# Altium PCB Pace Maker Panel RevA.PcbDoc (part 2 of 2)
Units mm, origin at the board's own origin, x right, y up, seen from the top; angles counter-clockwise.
Board outline 150.47 x 78.27 mm, 2 copper layers (Top Copper, Bottom Copper), stack 1.57 mm thick; 193 components, 124 nets, 564 pads, 154 vias.
Unrouted connection lines stored in the file: 2.
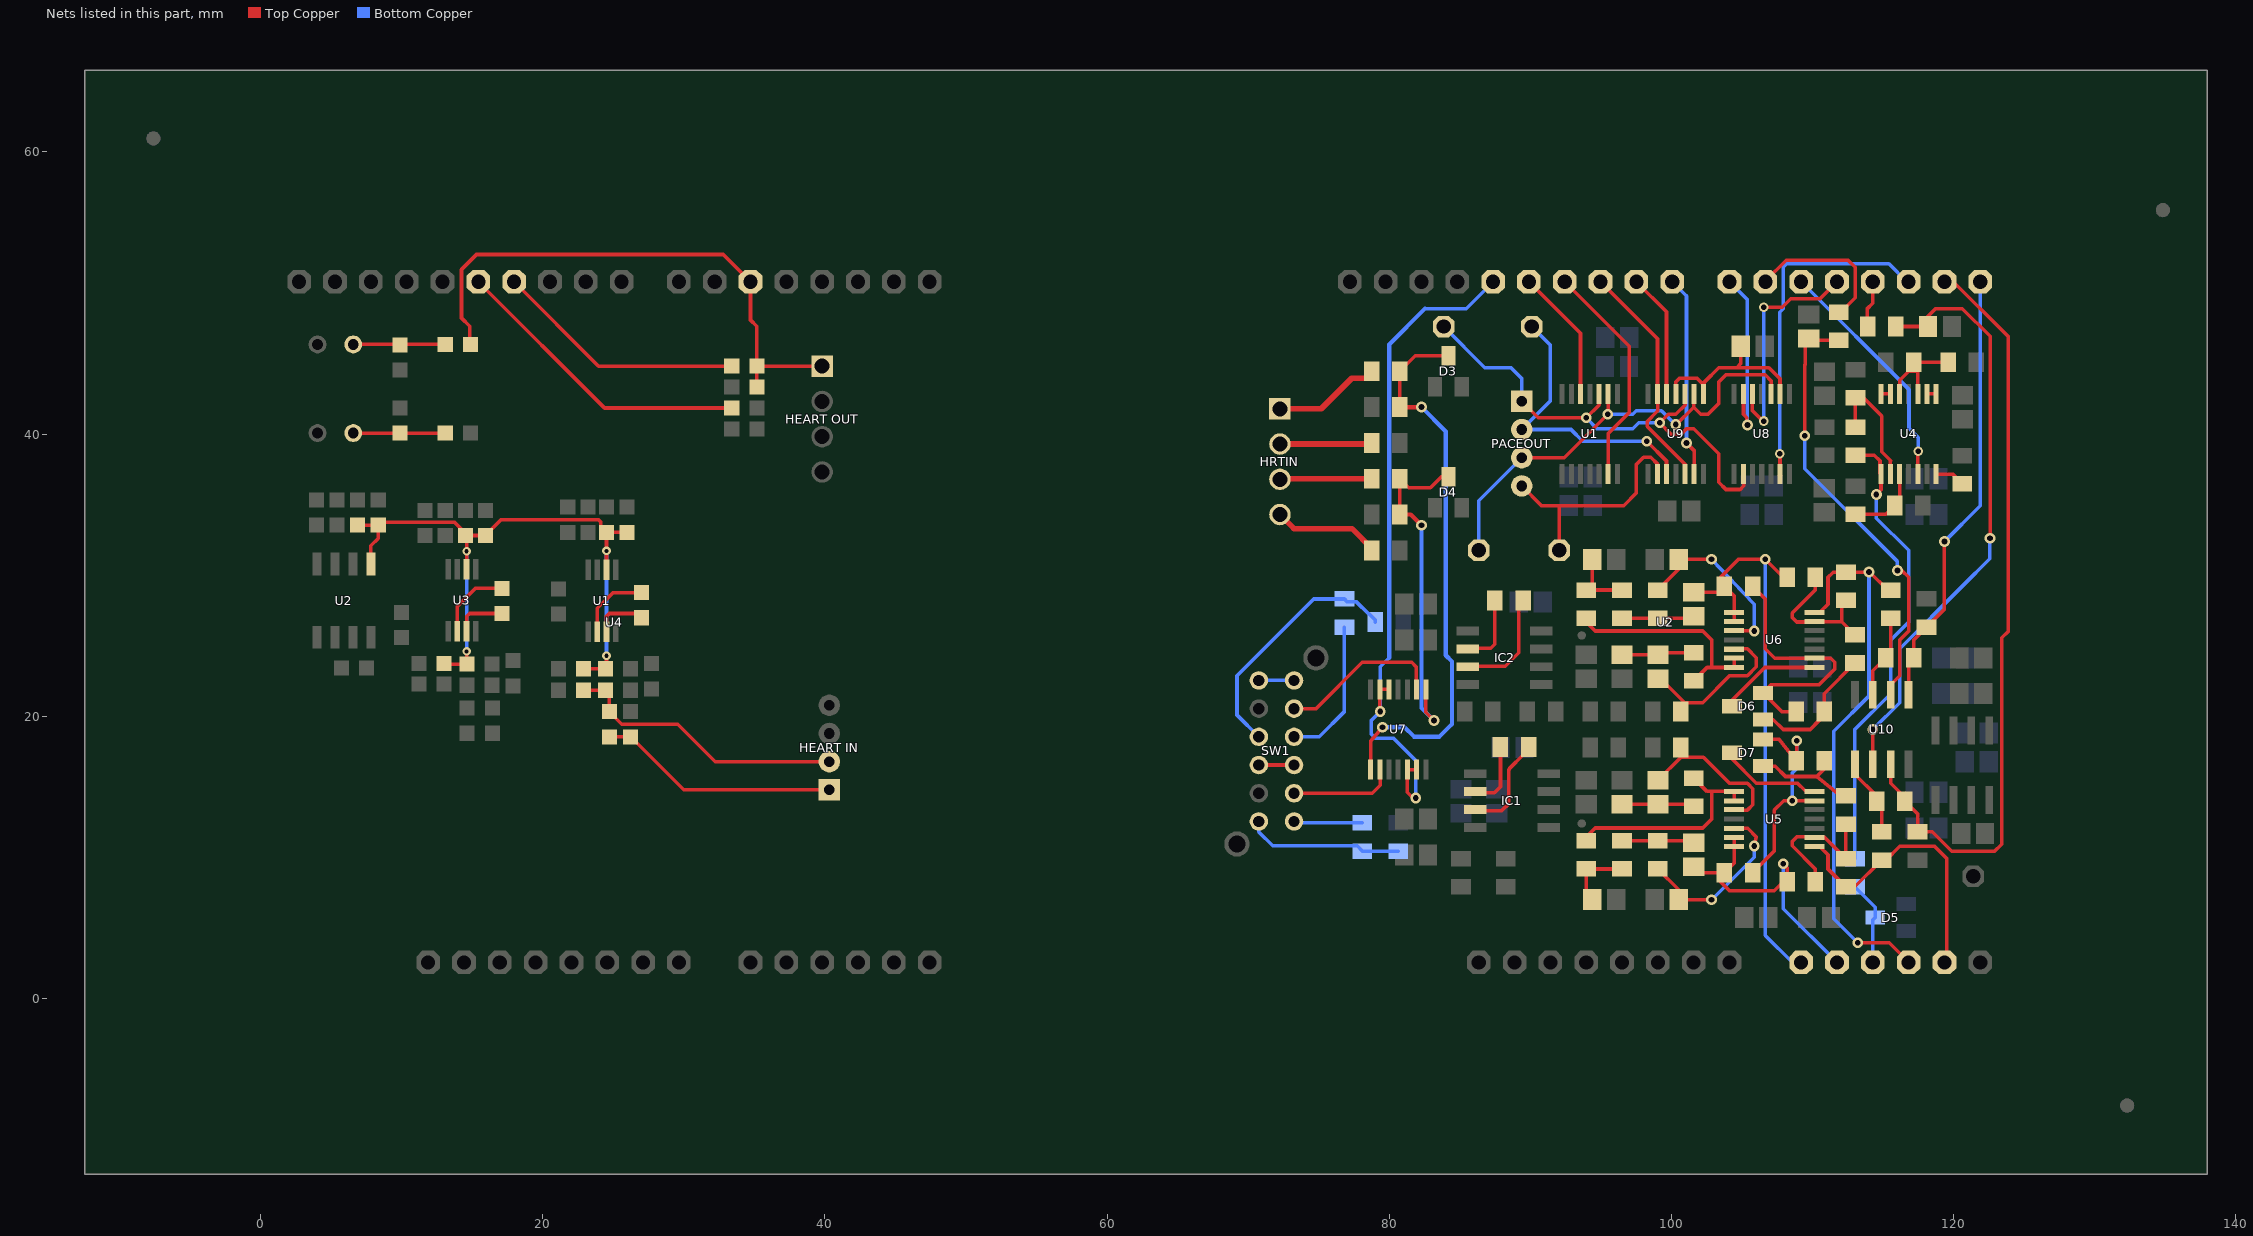
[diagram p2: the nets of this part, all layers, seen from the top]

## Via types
v1: diameter 0.762/0.762 (per signal layer), hole 0.406, Top Copper to Bottom Copper, 126 vias
v2: diameter 0.61, hole 0.305, Top Copper to Bottom Copper, 10 vias
v3: diameter 0.635, hole 0.381, Top Copper to Bottom Copper, 9 vias
v4: diameter 0.686, hole 0.33, Top Copper to Bottom Copper, 5 vias
v5: diameter 0.686, hole 0.381, Top Copper to Bottom Copper, 4 vias

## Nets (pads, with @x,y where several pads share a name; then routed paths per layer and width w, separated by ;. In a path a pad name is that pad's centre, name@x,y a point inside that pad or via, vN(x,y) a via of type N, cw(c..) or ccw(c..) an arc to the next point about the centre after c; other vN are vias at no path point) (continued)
NetC22_1: C22.1 U8.2 U9.8 U9.11 | length 13.4
  Top Copper w0.254: U9.11@100.33,42.85 100.33,43.688 100.584,43.942 101.854,43.942 102.286,43.51 U9.8@102.286,42.85 102.362,42.926 102.362,43.688 103.378,44.704 104.648,44.704 ; C22.1@104.941,46.228 104.941,44.997 104.648,44.704 ; U8.2@107.721,42.85 107.721,43.917 106.934,44.704 104.648,44.704
NetC23_2: C23.2 C25.1 R27.1 | length 5.1
  Top Copper w0.254: C23.2@96.52,13.755 C25.1@99.06,13.755 101.45,13.755 R27.1@101.6,13.605
NetC24_2: C24.2 C26.1 R28.1 | length 5.1
  Top Copper w0.254: C24.2@96.52,24.345 C26.1@99.06,24.345 99.21,24.495 R28.1@101.6,24.495
NetC25_2: C25.2 R25.2 U5.3 | length 11.7
  Top Copper w0.254: C25.2@99.06,15.455 R25.2@100.695,17.09 ; R25.2@100.695,17.78 R25.2@100.695,17.09 ; U5.3@104.47,13.36 104.496,13.335 105.41,13.335 105.791,13.716 105.791,14.859 105.41,15.24 104.14,15.24 102.29,17.09 R25.2@100.695,17.09
NetC26_2: C26.2 R26.2 U6.12 | length 12
  Top Copper w0.254: C26.2@99.06,22.645 99.275,22.645 R26.2@100.965,20.955 ; R26.2@100.695,20.32 100.965,20.59 R26.2@100.965,20.955 ; U6.12@104.47,24.74 104.496,24.765 105.41,24.765 106.045,24.13 106.045,23.495 105.41,22.86 104.14,22.86 102.235,20.955 R26.2@100.965,20.955
NetC29_1: C29.1 R29.2 R31.1 | length 4.9
  Top Copper w0.254: C29.1@94.4,6.985 93.98,7.405 R29.2@93.98,9.16 R31.1@96.52,9.16
NetC30_1: C30.1 R30.2 R32.1 | length 4.9
  Top Copper w0.254: C30.1@94.4,31.115 94.4,29.36 R30.2@93.98,28.94 R32.1@96.52,28.94
NetC31_1: C31.1 R33.2 U5.5 | length 12.7
  Top Copper w0.254: R33.2@99.06,9.16 100.545,7.675 C31.1@100.545,6.985 v1(102.87,6.985) ; U5.5@104.47,12.04 105.435,12.04 106.045,11.43 v1(105.886,10.795)
  Bottom Copper w0.254: v1(102.87,6.985) 105.886,10.001 v1(105.886,10.795)
NetC32_1: C32.1 R34.2 U6.10 | length 13.1
  Top Copper w0.254: R34.2@99.06,28.94 100.545,30.425 C32.1@100.545,31.115 v1(102.87,31.115) ; U6.10@104.47,26.06 106.02,26.06 v1(105.886,26.035)
  Bottom Copper w0.254: v1(102.87,31.115) 105.886,27.94 v1(105.886,26.035)
NetC34_1: C34.1 R31.2 R33.1 | length 5.1
  Top Copper w0.254: R31.2@96.52,11.16 R33.1@99.06,11.16 101.45,11.16 C34.1@101.6,11.01
NetC34_2: C34.2 R36.1 R40.1 U2.A1 U5.6 U5.7 | length 21.5
  Top Copper w0.254: C34.2@101.6,9.31 102.02,8.89 R36.1@103.775,8.89 ; U5.6@104.47,11.405 U5.7@104.47,10.744 104.47,9.585 R36.1@103.775,8.89 ; v1(107.95,9.525) 108.22,9.255 R40.1@108.22,8.255 108.22,8.525 107.315,7.62 104.14,7.62 103.505,8.255 103.505,8.62 R36.1@103.775,8.89
  Bottom Copper w0.254: v1(107.95,9.525) 107.95,6.35 U2.A1@111.76,2.54
NetC35_1: C35.1 R32.2 R34.1 | length 5.1
  Top Copper w0.254: R32.2@96.52,26.94 R34.1@99.06,26.94 101.45,26.94 C35.1@101.6,27.09
NetC35_2: C35.2 R35.1 R39.1 U2.A0 U6.8 U6.9 | length 41.7
  Top Copper w0.254: C35.2@101.6,28.79 103.355,28.79 R35.1@103.775,29.21 ; U6.9@104.47,26.695 U6.8@104.47,27.356 104.47,28.515 R35.1@103.775,29.21 ; R39.1@108.22,29.845 107.95,29.845 v1(106.68,31.115) 104.775,31.115 103.505,29.845 103.505,29.48 R35.1@103.775,29.21
  Bottom Copper w0.254: v1(106.68,31.115) 106.68,4.445 108.585,2.54 U2.A0@109.22,2.54
NetC37_1: C37.1 R41.1 U10.6 | length 42.2
  Top Copper w0.254: U10.6@114.3,16.586 v1(114.3,19.05) ; R41.1@115.935,47.625 C37.1@118.213,47.625 118.213,48.363 118.745,48.895 120.65,48.895 122.618,46.926 122.618,32.619 v1(122.604,32.604)
  Bottom Copper w0.254: v1(114.3,19.05) 116.205,20.955 116.205,24.765 120.666,29.226 122.604,31.164 v1(122.604,32.604)
NetC38_1: C38.1 R42.1 U10.2 | length 31.3
  Top Copper w0.254: v1(109.474,39.878) 109.474,44.895 109.498,44.919 109.498,46.52 C38.1@109.753,46.775 109.891,46.638 R42.1@111.887,46.638 ; U10.2@115.57,21.514 115.57,22.225 116.205,22.86 116.205,25.4 116.84,26.035 116.84,29.845 116.364,30.321 v1(116.046,30.321)
  Bottom Copper w0.254: v1(109.474,39.878) 109.474,37.529 116.046,30.956 v1(116.046,30.321)
NetD3_3: D3.3 R1.2@80.756,44.45 R5.2@80.756,41.91 U7.8 | length 40.5
  Top Copper w0.254: U7.8@78.689,16.205 78.689,18.205 v1(79.534,19.209) ; R5.2@80.756,41.91 R1.2@80.756,44.45 81.856,45.55 D3.3@84.201,45.55 D3.3@84.371,45.72
  Top Copper w0.305: R5.2@80.756,41.91 v1(82.296,41.91)
  Bottom Copper w0.305: v1(79.534,19.209) 81.097,19.209 81.764,18.542 83.566,18.542 84.455,19.431 84.455,23.876 84.023,24.308 84.023,40.183 v1(82.296,41.91)
NetD4_3: D4.3 R3.2@80.756,36.83 R6.2@80.756,34.29 U7.1 | length 25.1
  Top Copper w0.254: R6.2@80.756,34.29 R3.2@80.756,36.83 81.391,36.195 82.931,36.195 83.714,36.978 D4.3@84.201,36.978 ; U7.1@82.601,21.895 82.601,20.269 v1(83.185,19.685)
  Top Copper w0.305: R6.2@80.756,34.29 81.534,34.29 v1(82.296,33.528)
  Bottom Copper w0.305: v1(82.296,33.528) 82.296,20.574 v1(83.185,19.685)
NetD5_3: D5.3 R55.1 U2.A2 | length 6
  Bottom Copper w0.254: R55.1@113.03,7.89 114.47,6.45 D5.3@114.47,5.715 114.3,5.545 U2.A2@114.3,2.54
NetD6_1: D6.1 R37.2 R43.1 | length 9.7
  Top Copper w0.254: D6.1@106.51,19.751 107.249,19.751 107.95,19.05 109.855,19.05 110.49,19.685 110.49,19.955 R37.2@110.855,20.32 110.855,21.59 R43.1@113.03,23.765
NetD6_2: D6.2 R35.2 R37.1 U6.2 | length 19.3
  Top Copper w0.254: R35.2@105.775,29.21 106.68,28.305 106.68,24.765 107.34,24.105 U6.2@110.16,24.105 111.309,24.105 111.601,23.812 111.601,23.336 110.49,22.225 107.084,22.225 D6.2@106.51,21.651 107.841,20.32 R37.1@108.855,20.32
NetD6_3: D6.3 U6.1 | length 7.4
  Top Copper w0.254: D6.3@104.31,20.701 104.14,20.871 104.14,20.955 106.629,23.444 U6.1@110.16,23.444
NetD7_1: D7.1 R38.2 R44.1 | length 8.4
  Top Copper w0.254: D7.1@106.51,16.449 107.376,16.449 108.109,15.716 110.331,15.716 ; R38.2@110.855,16.828 111.125,16.875 111.125,16.51 110.331,15.716 ; R44.1@112.395,14.335 112.03,14.335 110.331,15.716
NetD7_2: D7.2 R36.2 R38.1 U5.13 | length 17.1
  Top Copper w0.254: R36.2@105.775,8.89 107.315,10.43 107.315,13.335 107.975,13.995 v1(108.585,13.995) U5.13@110.16,13.995 ; D7.2@106.51,18.349 107.651,18.349 R38.1@108.855,16.828 108.902,17.192 v1(108.902,18.256)
  Bottom Copper w0.254: v1(108.585,13.995) 108.585,15.967 108.902,16.285 v1(108.902,18.256)
NetD7_3: D7.3 U5.14 | length 7.2
  Top Copper w0.254: D7.3@104.31,17.399 104.31,16.975 106.045,15.24 108.966,15.24 109.499,14.707 110.109,14.707 U5.14@110.16,14.656
NetHRTIN_1: HRTIN.1 R1.1@78.756,44.45 | length 7.7
  Top Copper w0.406: HRTIN.1@72.263,41.79 75.191,41.79 77.354,43.953 78.409,43.953 78.756,44.3 R1.1@78.756,44.45
NetHRTIN_2: HRTIN.2 R2.1@78.756,39.37 | length 6.5
  Top Copper w0.406: HRTIN.2@72.263,39.29 78.676,39.29 R2.1@78.756,39.37
NetHRTIN_3: HRTIN.3 R3.1@78.756,36.83 | length 6.5
  Top Copper w0.406: HRTIN.3@72.263,36.79 72.303,36.83 R3.1@78.756,36.83
NetHRTIN_4: HRTIN.4 R4.1@78.756,31.75 | length 7.6
  Top Copper w0.406: HRTIN.4@72.263,34.29 73.26,33.293 77.362,33.293 78.756,31.9 R4.1@78.756,31.75
NetIC1_1: 
NetIC1_2: IC1.2 R19.1@87.9,17.8 | length 5
  Top Copper w0.254: IC1.2@85.9,14.57 87.47,14.57 87.9,15 R19.1@87.9,17.8
NetIC1_3: IC1.3 R19.2@89.9,17.8 | length 7.4
  Top Copper w0.254: IC1.3@85.9,13.3 88,13.3 88.5,13.8 88.5,16.145 cw(c88.754,16.145) 88.574,16.324 89.477,17.227 89.9,17.65 R19.2@89.9,17.8
NetIC1_8: 
NetIC2_1: 
NetIC2_2: IC2.2 R20.1@87.5,28.2 | length 4.9
  Top Copper w0.254: IC2.2@85.8,24.8 87.2,24.8 87.5,25.1 R20.1@87.5,28.2
NetIC2_3: IC2.3 R20.2@89.5,28.2 | length 7.4
  Top Copper w0.254: IC2.3@85.8,23.53 88.23,23.53 89.2,24.5 R20.2@89.2,28.1
NetIC2_8: 
NetJP2_1: JP2.1 PACEOUT.1 U1.3@94.894,42.85 U8.9 U9.10 | length 35
  Top Copper w0.254: PACEOUT.1@89.408,42.322 90.582,41.148 v1(93.98,41.148) 94.894,42.062 U1.3@94.894,42.85 ; U9.10@100.99,42.85 100.99,42.062 100.33,41.402 99.79,41.402 v1(99.187,40.799) 99.993,39.993 100.699,39.993 101.092,40.386 101.6,40.386 103.378,38.608 103.378,36.576 103.886,36.068 104.902,36.068 105.156,36.322 105.156,37.135 U8.9@105.131,37.16
  Bottom Copper w0.254: JP2.1@83.87,47.625 86.791,44.704 88.646,44.704 89.408,43.942 PACEOUT.1@89.408,42.322 ; v1(93.98,41.148) 94.742,40.386 97.282,40.386 97.695,40.799 v1(99.187,40.799)
NetJP3_1: JP3.1 PACEOUT.2 U9.3 | length 20.8
  Top Copper w0.254: v1(98.266,39.497) 99.67,38.094 U9.3@99.67,37.16
  Bottom Copper w0.254: JP3.1@90.12,47.625 91.44,46.305 91.44,42.354 PACEOUT.2@89.408,40.322 92.901,40.322 93.726,39.497 v1(98.266,39.497)
NetJP4_1: JP4.1 PACEOUT.3 U1.2@95.529,42.85 U8.3 U9.9 | length 33.6
  Top Copper w0.254: PACEOUT.3@89.408,38.322 92.424,38.322 v1(95.504,41.402) 95.529,41.427 U1.2@95.529,42.85 ; v1(100.33,40.679) 100.369,40.679 101.6,41.91 ; U9.9@101.625,42.85 101.6,42.824 101.6,41.91 ; U8.3@107.086,42.85 107.086,43.79 106.68,44.196 103.886,44.196 103.378,43.688 103.378,42.164 102.616,41.402 102.108,41.402 101.6,41.91
  Bottom Copper w0.254: JP4.1@86.36,31.75 86.36,35.274 PACEOUT.3@89.408,38.322 ; v1(95.504,41.402) 97.282,41.402 97.536,41.656 99.314,41.656 100.291,40.679 v1(100.33,40.679)
NetJP5_1: JP5.1 PACEOUT.4 U9.2 | length 16.9
  Top Copper w0.254: PACEOUT.4@89.408,36.322 90.805,34.925 92.075,34.925 ; JP5.1@92.075,31.75 92.075,34.925 ; U9.2@99.035,37.16 99.035,37.871 98.552,38.354 98.044,38.354 97.536,37.846 97.536,35.814 96.647,34.925 92.075,34.925
NetLED1_A: LED1.A LED3.A R13.2@13.074,46.355 | length 6.5
  Top Copper w0.254: LED3.A@6.553,46.355 10.211,46.355 R13.2@13.074,46.355
NetLED2_A: LED2.A LED4.A R14.2@13.074,40.068 | length 6.5
  Top Copper w0.254: LED4.A@6.553,40.068 LED2.A@9.855,40.068 R14.2@13.074,40.068
NetR4_1: R4.1@27,28.753 U1.2@23.861,25.99 | length 5.3
  Top Copper w0.254: U1.2@23.861,25.99 23.861,27.645 24.968,28.753 R4.1@27,28.753
NetR4_2: R4.2@27,26.975 U1.3@24.511,25.99 | length 3.9
  Top Copper w0.254: U1.3@24.511,25.99 24.511,27.071 24.717,27.277 26.547,27.277 26.594,27.229 26.695,27.229 R4.2@27.102,26.822
NetR7_1: R7.1@78.105,10.43 R8.2@80.645,10.43 SW1.1 | length 11.2
  Bottom Copper w0.254: SW1.1@70.765,12.53 70.765,11.785 71.755,10.795 77.74,10.795 R7.1@78.105,10.43 R8.2@80.645,10.43
NetR7_2: R7.2@78.105,12.43 SW1.7 | length 4.9
  Bottom Copper w0.254: SW1.7@73.265,12.53 73.365,12.43 R7.2@78.105,12.43
NetR9_1: R9.1@76.835,28.305 R10.2@79.01,26.67 SW1.4 | length 17.8
  Bottom Copper w0.254: SW1.4@70.765,18.53 69.215,20.08 69.215,22.86 74.66,28.305 R9.1@76.835,28.305 77.044,28.096 77.695,28.096 78.548,27.243 78.587,27.243 79.01,26.82 R10.2@79.01,26.67
NetR9_2: R9.2@76.835,26.305 SW1.10 | length 10.3
  Bottom Copper w0.254: SW1.10@73.265,18.53 75.045,18.53 76.835,20.32 R9.2@76.835,26.305
NetR10_1: R10.1@17.109,29.055 U3.2@13.934,26.006 | length 5.5
  Top Copper w0.254: U3.2@13.934,26.006 13.934,27.772 15.216,29.055 R10.1@17.109,29.055
NetR10_2: R10.2@17.109,27.277 U3.3@14.584,26.006 | length 3.7
  Top Copper w0.254: U3.3@14.584,26.006 14.605,26.027 14.605,27.071 14.811,27.277 R10.2@17.109,27.277
NetR12_2: R12.2@120.65,36.465 U4.7 | length 2.1
  Top Copper w0.254: U4.7@118.796,37.16 119.955,37.16 R12.2@120.65,36.465
NetR15_1: R15.1@33.39,44.813 U4.D11 | length 17.9
  Top Copper w0.254: U4.D11@17.958,50.8 23.945,44.813 R15.1@33.39,44.813
NetR16_1: R16.1@33.39,41.846 U4.D12 | length 21.7
  Top Copper w0.254: U4.D12@15.418,50.8 24.372,41.846 R16.1@33.39,41.846
NetR17_1: R17.1@113.081,34.306 R21.2 U4.3 | length 5.9
  Top Copper w0.254: R17.1@113.081,34.306 115.221,34.306 R21.2@115.84,34.925 ; R21.2@115.475,34.56 R21.2@115.84,34.925 ; U4.3@116.18,37.16 116.205,37.135 116.205,35.29 R21.2@115.84,34.925
NetR18_2: R18.2@113.068,42.561 R22.2 U4.2 | length 9
  Top Copper w0.254: R22.2@113.068,40.497 R18.2@113.068,42.561 113.395,42.815 114.935,41.275 114.935,38.735 115.57,38.1 115.545,38.075 U4.2@115.545,37.16
NetR22_1: R22.1 R55.2 U4.1 | length 32.8
  Top Copper w0.254: R22.1@113.068,38.497 114.411,38.497 114.808,38.1 114.808,37.236 U4.1@114.884,37.16 114.884,36.049 v1(114.554,35.719)
  Bottom Copper w0.254: R55.2@113.03,9.89 113.03,19.05 115.57,21.59 115.57,25.4 116.84,26.67 116.84,31.75 114.554,34.036 v1(114.554,35.719)
NetR27_2: R27.2 R29.1 U5.1 U5.2 | length 15.6
  Top Copper w0.254: R29.1@93.98,11.16 93.98,11.43 94.615,12.065 102.235,12.065 102.87,12.7 102.87,14.656 ; R27.2@101.6,15.605 102.549,14.656 102.87,14.656 ; U5.2@104.47,13.995 U5.1@104.47,14.656 102.87,14.656
NetR28_2: R28.2 R30.1 U6.13 U6.14 | length 15.6
  Top Copper w0.254: R30.1@93.98,26.94 93.98,26.67 94.615,26.035 102.235,26.035 102.87,25.4 102.87,23.444 ; R28.2@101.6,22.495 102.549,23.444 102.87,23.444 ; U6.13@104.47,24.105 U6.14@104.47,23.444 102.87,23.444
NetR39_2: R39.2 R43.2 R45.1 U6.6 | length 10.1
  Top Copper w0.254: R39.2@110.22,29.845 110.22,28.94 108.585,27.305 108.585,26.987 108.902,26.67 110.134,26.67 U6.6@110.16,26.695 112.1,26.695 ; R45.1@112.395,28.21 112.1,27.915 112.1,26.695 ; R43.2@113.03,25.765 112.1,26.695
NetR40_2: R40.2 R44.2 R46.1 U5.9 | length 10.6
  Top Copper w0.254: R40.2@110.22,8.255 110.22,9.16 108.585,10.795 108.585,11.112 108.902,11.43 110.134,11.43 U5.9@110.16,11.405 110.88,11.405 R46.1@112.395,9.89 R44.2@112.395,12.335
NetR41_2: R41.2 U2.D3 | length 3.9
  Top Copper w0.254: R41.2@113.935,47.625 113.894,47.666 113.894,48.87 114.3,49.276 U2.D3@114.3,50.8 U2.D3@113.935,50.435
NetR42_2: R42.2 U2.D6 | length 11
  Top Copper w0.254: U2.D6@106.68,50.8 106.68,50.851 108.153,52.324 112.547,52.324 113.055,51.816 113.055,49.656 112.46,49.061 R42.2@111.962,48.563
NetR45_2: R45.2 R48.2 U2.A3 U6.7 | length 40.5
  Top Copper w0.254: U6.7@110.16,27.356 110.541,27.356 111.125,27.94 111.125,29.845 111.49,30.21 R45.2@112.395,30.21 ; R45.2@112.442,30.162 R45.2@112.395,30.21 ; v1(113.23,3.92) 115.46,3.92 U2.A3@116.84,2.54 ; R48.2@115.57,28.94 115.364,28.94 114.094,30.21 v1(114.03,30.21) 113.53,30.21 R45.2@112.395,30.21
  Bottom Copper w0.254: v1(113.23,3.92) 111.53,5.62 111.53,18.92 114.03,21.42 v1(114.03,30.21)
NetR46_2: R46.2 R47.2 U2.A4 U5.8 | length 20.1
  Top Copper w0.254: U5.8@110.16,10.744 110.541,10.744 111.125,10.16 111.125,9.16 R46.2@112.395,7.89 113.03,7.89 R47.2@114.935,9.795 115.23,9.795 116.205,10.77 118.68,10.77 119.53,9.92 119.53,2.69 U2.A4@119.38,2.54
NetR47_1: R47.1 R49.2 U10.5 | length 5.6
  Top Copper w0.254: U10.5@113.03,16.586 113.03,15.875 114.57,14.335 R49.2@114.57,13.97 114.935,13.605 R47.1@114.935,11.795
NetR48_1: R48.1 R50.2 U10.3 | length 6.4
  Top Copper w0.254: U10.3@114.3,21.514 114.3,23.225 R50.2@115.205,24.13 ; R50.2@114.935,24.495 R50.2@115.205,24.13 ; R48.1@115.57,26.94 115.57,24.495 R50.2@115.205,24.13
NetR49_1: R49.1 R51.1 U2.D1 U10.7 | length 54.6
  Top Copper w0.254: U10.7@115.57,16.586 115.57,15.24 116.57,14.24 R49.1@116.57,13.97 117.475,13.065 R51.1@117.475,11.795 118.507,11.795 119.888,10.414 122.936,10.414 123.444,10.922 123.444,25.544 123.9,26 123.9,46.915 120.015,50.8 U2.D1@119.38,50.8
NetR50_1: R50.1 R52.1 U2.D0 U10.1 | length 31.4
  Top Copper w0.254: U10.1@116.84,21.514 116.84,23.86 R50.1@117.205,24.13 117.205,25.4 R52.1@118.11,26.305 119.38,27.575 v1(119.38,32.385)
  Bottom Copper w0.254: v1(119.38,32.385) 121.92,34.925 U2.D0@121.92,50.8
NetR53_1: R53.1 R54.2 U4.10 U4.12 | length 7.3
  Top Copper w0.254: U4.12@116.18,42.85 116.205,42.875 116.205,43.815 116.84,44.45 R54.2@117.5,44.45 ; U4.10@117.5,42.85 R54.2@117.5,44.45 ; R53.1@119.65,45.085 R54.2@117.205,45.085 117.5,44.79 R54.2@117.5,44.45
NetSW1_3: SW1.3 SW1.9 | length 2.5
  Top Copper w0.254: SW1.3@70.765,16.53 SW1.9@73.265,16.53
NetSW1_6: SW1.6 SW1.12 | length 2.5
  Bottom Copper w0.254: SW1.6@70.765,22.53 SW1.12@73.265,22.53
NetSW1_8: SW1.8 U7.9 | length 7.5
  Top Copper w0.254: SW1.8@73.265,14.53 78.815,14.53 79.375,15.09 79.375,15.575 U7.9@79.35,16.205
NetSW1_11: SW1.11 U7.2 | length 11.7
  Top Copper w0.254: SW1.11@73.265,20.53 74.823,20.53 78.105,23.812 81.597,23.812 81.915,23.495 81.915,22.525 U7.2@81.94,21.895
NetU1_5: U1.5@93.574,42.85 U2.D12 | length 9.5
  Top Copper w0.254: U2.D12@89.916,50.8 93.574,47.142 U1.5@93.574,42.85
NetU1_13: U1.13 U2.D11 | length 16.2
  Top Copper w0.254: U2.D11@92.456,50.8 97.028,46.228 97.028,41.528 95.529,40.029 U1.13@95.529,37.16
NetU2_D2: U2.D2 U8.13 | length 24.3
  Top Copper w0.254: v5(107.696,38.608) 107.721,38.583 U8.13@107.721,37.16
  Bottom Copper w0.254: v5(107.696,38.608) 107.696,48.641 107.95,48.895 107.95,51.816 108.204,52.07 115.443,52.07 116.713,50.8 U2.D2@116.84,50.8
NetU2_D4: U2.D4 U8.5 | length 16.3
  Top Copper w0.254: U8.5@105.766,42.85 105.766,41.656 106.502,40.919 v5(106.578,40.919) ; v5(106.578,48.997) 107.874,48.997 108.475,49.598 110.558,49.598 U2.D4@111.76,50.8
  Bottom Copper w0.254: v5(106.578,40.919) v5(106.578,48.997)
NetU2_D5: U2.D5 U4.5 | length 17.1
  Top Copper w0.254: U4.5@117.5,37.16 117.5,38.76 v5(117.526,38.786)
  Bottom Copper w0.254: U2.D5@109.22,50.8 116.865,43.155 116.865,40.411 117.526,39.751 v5(117.526,38.786)
NetU2_D7: U2.D7 U8.6 | length 13
  Top Copper w0.254: U8.6@105.131,42.85 105.131,41.4 105.365,41.165 105.365,40.685 v1(105.41,40.64)
  Bottom Copper w0.254: U2.D7@104.14,50.8 105.41,49.53 v1(105.41,40.64)
NetU2_D8: U2.D8 U9.6 | length 15.5
  Top Copper w0.254: v1(101.092,39.37) 101.625,38.837 U9.6@101.625,37.16
  Bottom Copper w0.254: v1(101.092,39.37) 101.092,49.784 100.965,49.911 ; 100.965,49.911 U2.D8@100.076,50.8 100.965,49.911
NetU2_D9: U2.D9 U9.12 | length 8.8
  Top Copper w0.254: U2.D9@97.536,50.8 99.67,48.666 U9.12@99.67,42.85
NetU2_D10: U2.D10 U9.5 U9.13 | length 16.8
  Top Copper w0.254: U2.D10@94.996,50.8 99.035,46.761 U9.13@99.035,42.85 99.06,42.824 99.06,41.656 98.298,40.894 98.298,40.538 100.99,37.846 U9.5@100.99,37.16
NetU2_D13: U2.D13 U7.5 U7.6 U7.12 U7.13 | length 49.2
  Top Copper w0.254: v1(79.375,20.32) 79.35,20.345 U7.6@79.35,21.895 U7.5@79.985,21.895 ; v1(81.9,14.2) 81.685,14.2 81.28,14.605 81.28,15.575 U7.12@81.305,16.205 U7.13@81.94,16.205
  Bottom Copper w0.254: 80.01,24.13 79.375,23.495 v1(79.375,20.32) 78.74,19.685 78.74,18.732 79.057,18.415 80.328,18.415 81.915,16.828 81.9,16.812 v1(81.9,14.2) ; 82.55,48.895 85.471,48.895 U2.D13@87.376,50.8
  Bottom Copper w0.305: 80.01,24.13 80.01,46.355 82.55,48.895
NetU4_8: U4.8 U4.9 | length 0.7
  Top Copper w0.254: U4.9@118.135,42.85 U4.8@118.796,42.85
NetU4_13: U4.13 U4.14 | length 0.7
  Top Copper w0.254: U4.14@114.884,42.85 U4.13@115.545,42.85
VENT+: "HEART IN.1" R1.2@26.226,18.532 R3.2@24.717,18.532 | length 17.2
  Top Copper w0.254: R3.2@24.717,18.532 R1.2@26.226,18.532 29.988,14.769 40.31,14.769
VENT-: "HEART IN.2" C4.1@22.891,21.834 R3.1@24.717,20.31 R5.1@24.447,21.834 | length 20.3
  Top Copper w0.254: C4.1@22.891,21.834 R5.1@24.447,21.834 24.717,21.565 R3.1@24.717,20.31 25.596,19.431 29.566,19.431 32.228,16.769 40.31,16.769
VENT_NAT: "HEART OUT.1" R13.1@14.852,46.355 R15.2@35.168,44.813 R17.2@35.168,43.329 U4.D5 | length 39.6
  Top Copper w0.254: R13.1@14.852,46.355 14.811,46.396 14.811,47.636 14.224,48.223 14.224,51.664 15.291,52.73 32.791,52.73 U4.D5@34.722,50.8 34.722,48.082 35.168,47.636 R15.2@35.168,44.813 ; R17.2@35.168,43.329 R15.2@35.168,44.813 ; 39.807,44.813 36.195,44.813 R15.2@35.168,44.813
VREF: C5.2@24.511,33.034 C6.2@25.961,33.034 C10.2@8.324,33.542 C11.2@6.862,33.542 C15.2@15.919,32.806 C16.2@14.496,32.806 R2.1@24.447,23.358 R6.2@22.891,23.358 R8.1@14.623,23.678 R12.2@12.979,23.714 U1.6@24.511,30.39 U2.1 U3.6@14.584,30.406 | length 48.7
  Top Copper w0.254: C11.2@6.862,33.542 C10.2@8.324,33.542 ; U2.1@7.798,30.785 7.798,32.069 8.324,32.596 C10.2@8.324,33.542 ; R12.2@12.979,23.714 13.015,23.678 R8.1@14.623,23.678 14.584,23.717 v2(14.584,24.587) ; C16.2@14.469,33.006 13.745,33.731 8.514,33.731 C10.2@8.324,33.542 ; U3.6@14.584,30.406 v2(14.584,31.699) 14.584,32.718 C16.2@14.496,32.806 C15.2@15.919,32.806 17.048,33.934 23.913,33.934 24.114,33.734 24.114,33.431 C5.2@24.511,33.034 ; R6.2@22.53,23.719 R6.2@22.891,23.358 R2.1@24.447,23.358 24.511,23.421 v2(24.511,24.282) ; U1.6@24.511,30.39 v2(24.511,31.712) C5.2@24.511,33.034 ; C6.2@25.961,33.034 C5.2@24.511,33.034
  Bottom Copper w0.254: v2(14.584,24.587) v2(14.584,31.699) ; v2(24.511,24.282) v2(24.511,31.712)
pads on no net: D5.2 Designator5.0 Designator6.0 Designator7.0 Designator8.0 Designator9.0 Designator10.0 U1.6@92.939,42.85 U2.4 U2.5 U2.6 U2.7 U2.A5 U2.AREF U2.IOREF U2.RESERVED U2.RESET U2.SCL U2.SDA U2.VIN U3.4@118.745,18.974 U3.5@118.745,14.046 U3.6@120.015,14.046 U3.7@121.285,14.046 U4.A2 U4.A3 U4.A4 U4.A5 U4.AREF U4.D0 U4.D1 U4.D2 U4.D4 U4.D6 U4.D7 U4.D8 U4.D9 U4.D10 U4.D13 U4.IOREF U4.RESERVED U4.RESET U4.SCL U4.SDA U4.VIN

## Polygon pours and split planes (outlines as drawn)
GND on Top Copper "Polygon_1_Net_GND" (solid, remove dead copper, pour order 5): 63.754,53.33 63.5,0 125.273,0 125.273,53.076
GND on Top Copper "gndtop" (solid, remove dead copper, pour order 3): 0,0 50.775,0 50.775,53.33 0,53.33
GND on Top Copper "GND_L01_P001" (solid, remove dead copper, pour order 1): -5.486,0.533
GND on Bottom Copper "Polygon_1_Net_GND" (solid, remove dead copper, pour order 6): 63.527,53.33 63.271,-0.295 125.044,-0.295 125.044,53.33
GND on Bottom Copper "gndtop" (solid, remove dead copper, pour order 4): 0,0 50.775,0 50.775,53.33 0,53.33

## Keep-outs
Keep-Out Layer:
  lines w0.051: -12.471,53.341 137.744,53.332 ; 0,-12.445 0,65.787 ; 50.765,-12.47 50.77,65.802 ; 63.5,-12.47 63.5,65.802 ; 125.517,-11.962 125.522,66.31 ; 137.744,-0.008 -12.471,0.001 ; -12.471,0 -12.471,-12.471 0,-12.471 50.775,-12.471 137.998,-12.471 137.998,0 137.998,53.33 137.998,65.801 50.775,65.801 0,65.801 -12.471,65.801 -12.471,53.33 -12.471,0

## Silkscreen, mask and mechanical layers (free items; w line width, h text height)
Top Overlay:
  text "V+" at 44.45,44.392 h1.5
  text "VENT" at 2.233,44.044 h1.5 r90
  text "V-" at 44.475,41.892 h1.5
  text "V+" at 84.887,41.351 h1.5
  text "V+" at 66.065,41.275 h2.5
  text "V-" at 84.887,39.954 h1.5
  text "A+" at 44.475,39.392 h1.5
  text "V-" at 66.142,38.735 h2.5
  text "ATR" at 2.184,38.557 h1.5 r90
  text "A+" at 84.887,38.506 h1.5
  text "A-" at 84.887,37.084 h1.5
  text "A-" at 44.45,36.902 h1.5
  text "A+" at 66.065,36.195 h2.5
  text "A-" at 66.116,33.833 h2.5
  text "ATR" at 88.5,29.5 h1.5
  text "X1" at 64.313,23.647 h1.5
  text "A-" at 43.815,20.574 h1.5
  text "A+" at 43.866,18.26 h1.5
  text "V-" at 43.942,16.053 h1.5
  text "VENT" at 84.9,13.8 h1.5 r90
  text "V+" at 43.967,13.716 h1.5
  text "X100" at 64.592,12.319 h1.5
  text "HEART / REV.A" at 1.111,9.982 h2.03
  text "PACEMAKER  REV 3.0" at 72.6,1.6 h1.5
Mechanical 1:
  lines w0: 63.5,0 63.5,53.076 125.273,53.33 125.273,0 63.5,0
V-Cut:
  lines w0.051: -12.471,0 137.744,-0.01 ; -12.471,53.34 137.744,53.33 ; 0,-12.446 0,65.786 ; 50.765,-12.471 50.77,65.801 ; 63.5,-12.471 63.5,65.801 ; 125.517,-11.963 125.522,66.309
Mechanical 13:
  circle w0.013: c61.5,3.5 r0.25
  circle w0.013: c3.5,3.5 r0.25
  circle w0.013: c23.61,2.23 r0.8
  circle w0.013: c23.61,4.77 r0.8
  circle w0.013: c8.37,4.77 r0.8
  circle w0.013: c10.91,4.77 r0.8
  circle w0.013: c13.45,4.77 r0.8
  circle w0.013: c15.99,4.77 r0.8
  circle w0.013: c18.53,4.77 r0.8
  circle w0.013: c21.07,4.77 r0.8
  circle w0.013: c26.15,4.77 r0.8
  circle w0.013: c28.69,4.77 r0.8
  circle w0.013: c31.23,4.77 r0.8
  circle w0.013: c33.77,4.77 r0.8
  circle w0.013: c36.31,4.77 r0.8
  circle w0.013: c38.85,4.77 r0.8
  circle w0.013: c41.39,4.77 r0.8
  circle w0.013: c43.93,4.77 r0.8
  circle w0.013: c46.47,4.77 r0.8
  circle w0.013: c49.01,4.77 r0.8
  circle w0.013: c51.55,4.77 r0.8
  circle w0.013: c54.09,4.77 r0.8
  circle w0.013: c8.37,2.23 r0.8
  circle w0.013: c10.91,2.23 r0.8
  circle w0.013: c13.45,2.23 r0.8
  circle w0.013: c15.99,2.23 r0.8
  circle w0.013: c18.53,2.23 r0.8
  circle w0.013: c21.07,2.23 r0.8
  circle w0.013: c26.15,2.23 r0.8
  circle w0.013: c28.69,2.23 r0.8
  circle w0.013: c31.23,2.23 r0.8
  circle w0.013: c33.77,2.23 r0.8
  circle w0.013: c36.31,2.23 r0.8
  circle w0.013: c38.85,2.23 r0.8
  circle w0.013: c41.39,2.23 r0.8
  circle w0.013: c43.93,2.23 r0.8
  circle w0.013: c46.47,2.23 r0.8
  circle w0.013: c49.01,2.23 r0.8
  circle w0.013: c51.55,2.23 r0.8
  circle w0.013: c54.09,2.23 r0.8
  circle w0.013: c56.63,2.23 r0.8
  circle w0.013: c61.5,3.5 r0.25
  circle w0.013: c3.5,3.5 r0.25
  circle w0.013: c61.5,52.5 r0.25
  circle w0.013: c3.5,52.5 r0.25
  circle w0.013: c23.61,2.23 r0.8
  circle w0.013: c23.61,4.77 r0.8
  circle w0.013: c8.37,4.77 r0.8
  circle w0.013: c10.91,4.77 r0.8
  circle w0.013: c13.45,4.77 r0.8
  circle w0.013: c15.99,4.77 r0.8
  circle w0.013: c18.53,4.77 r0.8
  circle w0.013: c21.07,4.77 r0.8
  circle w0.013: c26.15,4.77 r0.8
  circle w0.013: c28.69,4.77 r0.8
  circle w0.013: c31.23,4.77 r0.8
  circle w0.013: c33.77,4.77 r0.8
  circle w0.013: c36.31,4.77 r0.8
  circle w0.013: c38.85,4.77 r0.8
  circle w0.013: c41.39,4.77 r0.8
  circle w0.013: c43.93,4.77 r0.8
  circle w0.013: c46.47,4.77 r0.8
  circle w0.013: c49.01,4.77 r0.8
  circle w0.013: c51.55,4.77 r0.8
  circle w0.013: c54.09,4.77 r0.8
  circle w0.013: c8.37,2.23 r0.8
  circle w0.013: c10.91,2.23 r0.8
  circle w0.013: c13.45,2.23 r0.8
  circle w0.013: c15.99,2.23 r0.8
  circle w0.013: c18.53,2.23 r0.8
  circle w0.013: c21.07,2.23 r0.8
  circle w0.013: c26.15,2.23 r0.8
  circle w0.013: c28.69,2.23 r0.8
  circle w0.013: c31.23,2.23 r0.8
  circle w0.013: c33.77,2.23 r0.8
  circle w0.013: c36.31,2.23 r0.8
  circle w0.013: c38.85,2.23 r0.8
  circle w0.013: c41.39,2.23 r0.8
  circle w0.013: c43.93,2.23 r0.8
  circle w0.013: c46.47,2.23 r0.8
  circle w0.013: c49.01,2.23 r0.8
  circle w0.013: c51.55,2.23 r0.8
  circle w0.013: c54.09,2.23 r0.8
  circle w0.013: c56.63,2.23 r0.8
  lines w0.013: 0,3 ccw(c3,3) 3,0 ; 55.83,3.97 55.83,5.57 ; 55.83,3.97 57.43,3.97 ; 55.83,3.97 55.83,5.57 ; 55.83,3.97 57.43,3.97 ; 55.83,5.57 57.43,5.57 ; 55.83,5.57 57.43,5.57 ; 57.43,3.97 57.43,5.57 ; 57.43,3.97 57.43,5.57 ; 7.1,1 57.9,1 57.9,6 7.1,6 7.1,1
Drill Drawing:
  circle w0.152: c-11.561,97.389 r0.339
  circle w0.152: c-11.561,97.389 r0.564
  circle w0.152: c-11.561,87.229 r0.564
  lines w0.152: -12.125,76.505 -10.996,76.505 -10.996,77.634 -12.125,77.634 -12.125,76.505 ; -12.125,80.174 -10.996,80.174 -11.561,79.045 -12.125,80.174 ; -12.125,81.585 -11.561,81.867 -10.996,81.585 -11.278,82.149 -10.996,82.714 -11.561,82.431 -12.125,82.714 -11.843,82.149 -12.125,81.585 ; -12.125,84.125 -12.125,84.407 -11.843,84.689 -12.125,84.971 -12.125,85.254 -11.843,85.254 -11.561,84.971 -11.278,85.254 -10.996,85.254 -10.996,84.971 -11.278,84.689 -10.996,84.407 -10.996,84.125 -11.278,84.125 -11.561,84.407 -11.843,84.125 -12.125,84.125 ; -12.125,89.487 -11.843,89.487 -11.561,89.205 -11.278,89.487 -10.996,89.487 -11.278,89.769 -10.996,90.051 -11.278,90.051 -11.561,90.334 -11.843,90.051 -12.125,90.051 -11.843,89.769 -12.125,89.487 ; -12.125,91.745 -10.996,91.745 -10.996,92.874 -12.125,92.874 -12.125,91.745 ; -12.125,94.567 -11.843,94.567 -11.843,94.285 -11.278,94.285 -11.278,94.567 -10.996,94.567 -10.996,95.131 -11.278,95.131 -11.278,95.414 -11.843,95.414 -11.843,95.131 -12.125,95.131 -12.125,94.567 ; -12.125,99.929 -11.561,99.365 -10.996,99.929 -11.561,100.494 -12.125,99.929 ; -11.899,76.731 -11.222,76.731 -11.222,77.408 -11.899,77.408 -11.899,76.731
  lines w0.254: -13.132,75.743 111.768,75.743 ; -13.132,101.143 111.768,101.143 ; -3.858,73.203 -3.858,103.683 ; 6.265,73.203 6.265,103.683 ; 24.853,73.203 24.853,103.683 ; 33.365,73.203 33.365,103.683 ; 45.736,73.203 45.736,103.683 ; 73.126,73.203 73.126,103.683 ; 83.06,73.203 83.06,103.683 ; 95.635,73.203 95.635,103.683 ; -13.132,73.203 111.768,73.203 111.768,103.683 -13.132,103.683 -13.132,73.203
  text "Symbol" at -11.608,101.905 h1.22
  text "Count" at -3.096,101.905 h1.22
  text "Hole Size" at 7.027,101.905 h1.22
  text "Plated" at 25.615,101.905 h1.22
  text "Hole Type" at 34.127,101.905 h1.22
  text "Drill Layer Pair" at 46.498,101.905 h1.22
  text "Via/Pad" at 73.888,101.905 h1.22
  text "Pad Shape" at 83.822,101.905 h1.22
  text "Template" at 96.397,101.905 h1.22
  text "2" at -3.096,99.365 h1.02
  text "47.24mil (1.200mm)" at 7.027,99.365 h1.02
  text "PTH" at 25.615,99.365 h1.02
  text "Round" at 34.127,99.365 h1.02
  text "Top Copper - Bottom Copper" at 46.498,99.365 h1.02
  text "Pad" at 73.888,99.365 h1.02
  text "Rounded" at 83.822,99.365 h1.02
  text "c180h120z0" at 96.397,99.365 h1.02
  text "5" at -3.096,96.825 h1.02
  text "13.00mil (0.330mm)" at 7.027,96.825 h1.02
  text "PTH" at 25.615,96.825 h1.02
  text "Round" at 34.127,96.825 h1.02
  text "Top Copper - Bottom Copper" at 46.498,96.825 h1.02
  text "Via" at 73.888,96.825 h1.02
  text "Rounded" at 83.822,96.825 h1.02
  text "v69h33" at 96.397,96.825 h1.02
  text "5" at -3.096,94.285 h1.02
  text "40.00mil (1.016mm)" at 7.027,94.285 h1.02
  text "PTH" at 25.615,94.285 h1.02
  text "Round" at 34.127,94.285 h1.02
  text "Top Copper - Bottom Copper" at 46.498,94.285 h1.02
  text "Pad" at 73.888,94.285 h1.02
  text "Rounded" at 83.822,94.285 h1.02
  text "s152h102c50zc0" at 96.397,94.285 h1.02
  text "8" at -3.096,91.745 h1.02
  text "42.00mil (1.067mm)" at 7.027,91.745 h1.02
  text "PTH" at 25.615,91.745 h1.02
  text "Round" at 34.127,91.745 h1.02
  text "Top Copper - Bottom Copper" at 46.498,91.745 h1.02
  text "Pad" at 73.888,91.745 h1.02
  text "(Mixed)" at 83.822,91.745 h1.02
  text "(Mixed)" at 96.397,91.745 h1.02
  text "10" at -3.096,89.205 h1.02
  text "12.00mil (0.305mm)" at 7.027,89.205 h1.02
  text "PTH" at 25.615,89.205 h1.02
  text "Round" at 34.127,89.205 h1.02
  text "Top Copper - Bottom Copper" at 46.498,89.205 h1.02
  text "Via" at 73.888,89.205 h1.02
  text "Rounded" at 83.822,89.205 h1.02
  text "v61h30" at 96.397,89.205 h1.02
  text "12" at -3.096,86.665 h1.02
  text "30.00mil (0.762mm)" at 7.027,86.665 h1.02
  text "PTH" at 25.615,86.665 h1.02
  text "Round" at 34.127,86.665 h1.02
  text "Top Copper - Bottom Copper" at 46.498,86.665 h1.02
  text "Pad" at 73.888,86.665 h1.02
  text "Rounded" at 83.822,86.665 h1.02
  text "(Mixed)" at 96.397,86.665 h1.02
  text "12" at -3.096,84.125 h1.02
  text "31.50mil (0.800mm)" at 7.027,84.125 h1.02
  text "PTH" at 25.615,84.125 h1.02
  text "Round" at 34.127,84.125 h1.02
  text "Top Copper - Bottom Copper" at 46.498,84.125 h1.02
  text "Pad" at 73.888,84.125 h1.02
  text "Rounded" at 83.822,84.125 h1.02
  text "c131h80z0" at 96.397,84.125 h1.02
  text "13" at -3.096,81.585 h1.02
  text "15.00mil (0.381mm)" at 7.027,81.585 h1.02
  text "PTH" at 25.615,81.585 h1.02
  text "Round" at 34.127,81.585 h1.02
  text "Top Copper - Bottom Copper" at 46.498,81.585 h1.02
  text "Via" at 73.888,81.585 h1.02
  text "Rounded" at 83.822,81.585 h1.02
  text "(Mixed)" at 96.397,81.585 h1.02
  text "64" at -3.096,79.045 h1.02
  text "39.37mil (1.000mm)" at 7.027,79.045 h1.02
  text "PTH" at 25.615,79.045 h1.02
  text "Round" at 34.127,79.045 h1.02
  text "Top Copper - Bottom Copper" at 46.498,79.045 h1.02
  text "Pad" at 73.888,79.045 h1.02
  text "(Mixed)" at 83.822,79.045 h1.02
  text "(Mixed)" at 96.397,79.045 h1.02
  text "126" at -3.096,76.505 h1.02
  text "16.00mil (0.406mm)" at 7.027,76.505 h1.02
  text "PTH" at 25.615,76.505 h1.02
  text "Round" at 34.127,76.505 h1.02
  text "Top Copper - Bottom Copper" at 46.498,76.505 h1.02
  text "Via" at 73.888,76.505 h1.02
  text "Rounded" at 83.822,76.505 h1.02
  text "v76h41" at 96.397,76.505 h1.02
  text "257 Total" at -3.096,73.965 h1.02
Mechanical 34:
  circle w0.127: c70.612,46.672 r0.355
  circle w0.127: c70.612,47.625 r0.355
  circle w0.127: c70.612,49.53 r0.355
  circle w0.127: c70.612,48.578 r0.355
  circle w0.305: c71.755,45.402 r0.159
  circle w0.305: c69.596,45.402 r0.159
  circle w0.305: c71.882,50.8 r0.159
  circle w0.305: c69.342,50.8 r0.159
  lines w0.127: 69.362,50.82 69.662,50.82 70.562,49.92 ; 69.621,45.402 69.621,45.25 70.117,44.755 72.06,44.755 72.441,45.136 72.441,45.974 70.955,47.46 70.955,47.498 ; 70.726,46.355 71.615,45.466 71.628,45.466 ; 70.962,48.72 71.862,49.62 71.862,50.82 ; 68.389,44.133 68.389,52.07 75.374,52.07 75.374,49.371 75.374,44.133 68.389,44.133
  lines w0.305: 75.374,49.371 85.196,49.371 cw(c85.196,49.244) 85.286,49.334 ; 85.268,49.327 86.449,48.146 86.449,46.126 87.782,44.793 87.884,44.895 87.884,45.466 ; 87.122,44.958 87.63,45.466 87.63,45.212 ; 87.884,44.704 87.122,44.704 ; 87.122,44.704 87.63,45.212 ; 87.122,44.704 86.614,44.704 87.884,45.974 87.884,45.466 ; 87.63,45.212 87.884,45.466 ; 65.024,27.432 65.024,30.48 79.502,30.48 79.502,27.432 65.024,27.432
  text "V+" at 69.183,49.371 h0.79
  text "V-" at 69.183,48.419 h0.79
  text "A+" at 69.183,47.466 h0.79
  text "A-" at 69.183,46.514 h0.79
  text "PACING PINOUT" at 74.898,44.926 h0.94 r90
  text "R_HEART" at 75.813,44.926 h0.94 r90
  text "U8" at 108.718,44.437 h0.94 r270
  text "U1" at 96.774,44.355 h0.94 r270
  text "V+" at 64.389,41.275 h1.97
  text "V-" at 64.389,38.735 h1.97
  text "U9" at 97.409,36.703 h0.94 r90
  text "A+" at 64.389,36.195 h1.97
  text "U4" at 114.459,36.195 h0.94 r90
  text "A-" at 64.389,33.655 h1.97
  text "3.3V ONLY" at 66.193,28.179 h1.4
  text "IC2" at 85.725,26.987 h0.94
  text "x1" at 66.167,25.781 h1.08 r270
  text "ATR" at 85.09,22.86 h1.57 r90
  text "U6" at 111.125,22.86 h0.94 r180
  text "U10" at 117.792,21.431 h0.94 r270
  text "U7" at 83.502,21.273 h0.94
  text "Attenuation" at 66.294,20.828 h0.65 r270
  text "U3" at 123.349,19.367 h0.94 r270
  text "IC1" at 85.566,16.51 h0.94
  text "U5" at 103.822,15.24 h0.94
  text "VENT" at 85.09,12.065 h1.57 r90
  text "x100" at 66.421,10.795 h1.08 r270
  text "GND" at 120.015,5.715 h1.97
  text "pacemaker_v2_rev2" at 68.961,1.524 h0.86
